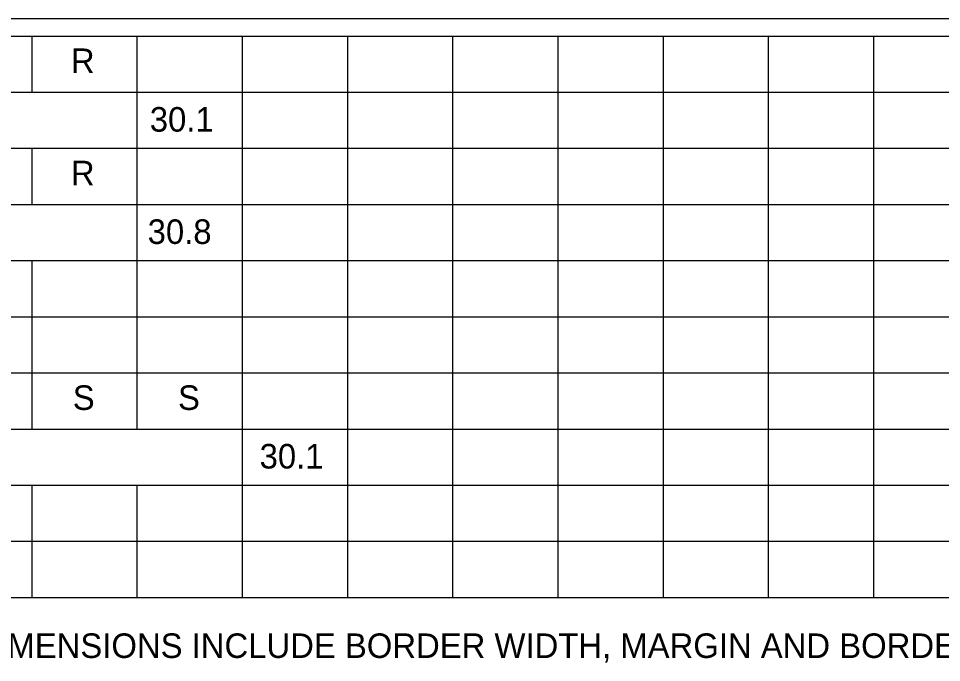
# Model space of a CAD drawing. Extents: x 10268312 to 10268471, y 2141099 to 2141204.
# Drawn here: x 10268354.6 to 10268380.92, y 2141110.37 to 2141128.73 of the extents above; entities that cross this region are included whole.
import ezdxf

# ---------------------------------------------------------------- set-up
doc = ezdxf.new("R2010")
doc.units = 0
for name, color, linetype in [('SumBoxLines_dp', 7, 'Continuous'), ('SumBoxLinesMin_dp', 7, 'Continuous'), ('TextLabel', 7, 'Continuous')]:
    doc.layers.add(name, color=color, linetype=linetype)

msp = doc.modelspace()

# ---------------------------------------------------------------- linework, layer by layer
at = {"layer": 'SumBoxLines_dp'}
for p, q in [((10268341.73, 2141128.728), (10268470.98, 2141128.728)), ((10268318.48, 2141128.228), (10268470.98, 2141128.228)), ((10268354.98, 2141128.228), (10268354.98, 2141126.628)), ((10268357.98, 2141128.228), (10268357.98, 2141121.828)), ((10268360.98, 2141128.228), (10268360.98, 2141121.828)), ((10268363.98, 2141128.228), (10268363.98, 2141125.028)), ((10268366.98, 2141128.228), (10268366.98, 2141125.028)), ((10268369.98, 2141128.228), (10268369.98, 2141121.828)), ((10268372.98, 2141128.228), (10268372.98, 2141121.828)), ((10268375.98, 2141128.228), (10268375.98, 2141121.828)), ((10268378.98, 2141128.228), (10268378.98, 2141121.828)), ((10268318.48, 2141125.028), (10268470.98, 2141125.028)), ((10268354.98, 2141125.028), (10268354.98, 2141123.428)), ((10268363.98, 2141125.028), (10268363.98, 2141121.828)), ((10268366.98, 2141125.028), (10268366.98, 2141121.828)), ((10268318.48, 2141121.828), (10268470.98, 2141121.828)), ((10268354.98, 2141121.828), (10268354.98, 2141117.028)), ((10268357.98, 2141121.828), (10268357.98, 2141117.028)), ((10268360.98, 2141121.828), (10268360.98, 2141112.228)), ((10268363.98, 2141121.828), (10268363.98, 2141112.228)), ((10268366.98, 2141121.828), (10268366.98, 2141112.228)), ((10268369.98, 2141121.828), (10268369.98, 2141112.228)), ((10268372.98, 2141121.828), (10268372.98, 2141112.228)), ((10268375.98, 2141121.828), (10268375.98, 2141112.228)), ((10268378.98, 2141121.828), (10268378.98, 2141112.228)), ((10268318.48, 2141118.628), (10268470.98, 2141118.628)), ((10268318.48, 2141115.428), (10268470.98, 2141115.428)), ((10268354.98, 2141115.428), (10268354.98, 2141112.228)), ((10268357.98, 2141115.428), (10268357.98, 2141112.228)), ((10268318.48, 2141112.228), (10268470.98, 2141112.228))]:
    msp.add_line(p, q, dxfattribs=at)
at = {"layer": 'SumBoxLinesMin_dp'}
for p, q in [((10268318.48, 2141126.628), (10268470.98, 2141126.628)), ((10268318.48, 2141123.428), (10268470.98, 2141123.428)), ((10268318.48, 2141120.228), (10268470.98, 2141120.228)), ((10268318.48, 2141117.028), (10268470.98, 2141117.028)), ((10268318.48, 2141113.828), (10268470.98, 2141113.828))]:
    msp.add_line(p, q, dxfattribs=at)

# ---------------------------------------------------------------- texts
at = {"layer": 'TextLabel'}
for s, height, p in [('R', 0.7, (10268356.097, 2141127.173)), ('30.1', 0.7, (10268358.346, 2141125.503)), ('R', 0.7, (10268356.097, 2141123.973)), ('30.8', 0.7, (10268358.285, 2141122.303)), ('S', 0.7, (10268356.15, 2141117.573)), ('S', 0.7, (10268359.15, 2141117.573)), ('30.1', 0.7, (10268361.477, 2141115.903)), ('NOTE:  WIDTH - HORIZONTAL SPACING DIMENSIONS ARE IN INCHES.  END DIMENSIONS INCLUDE BORDER WIDTH, MARGIN AND BORDER RECESS.', 0.700021, (10268319.18, 2141110.504))]:
    msp.add_text(s, height=height, dxfattribs=at).set_placement(p)

doc.saveas('drawing.dxf')
